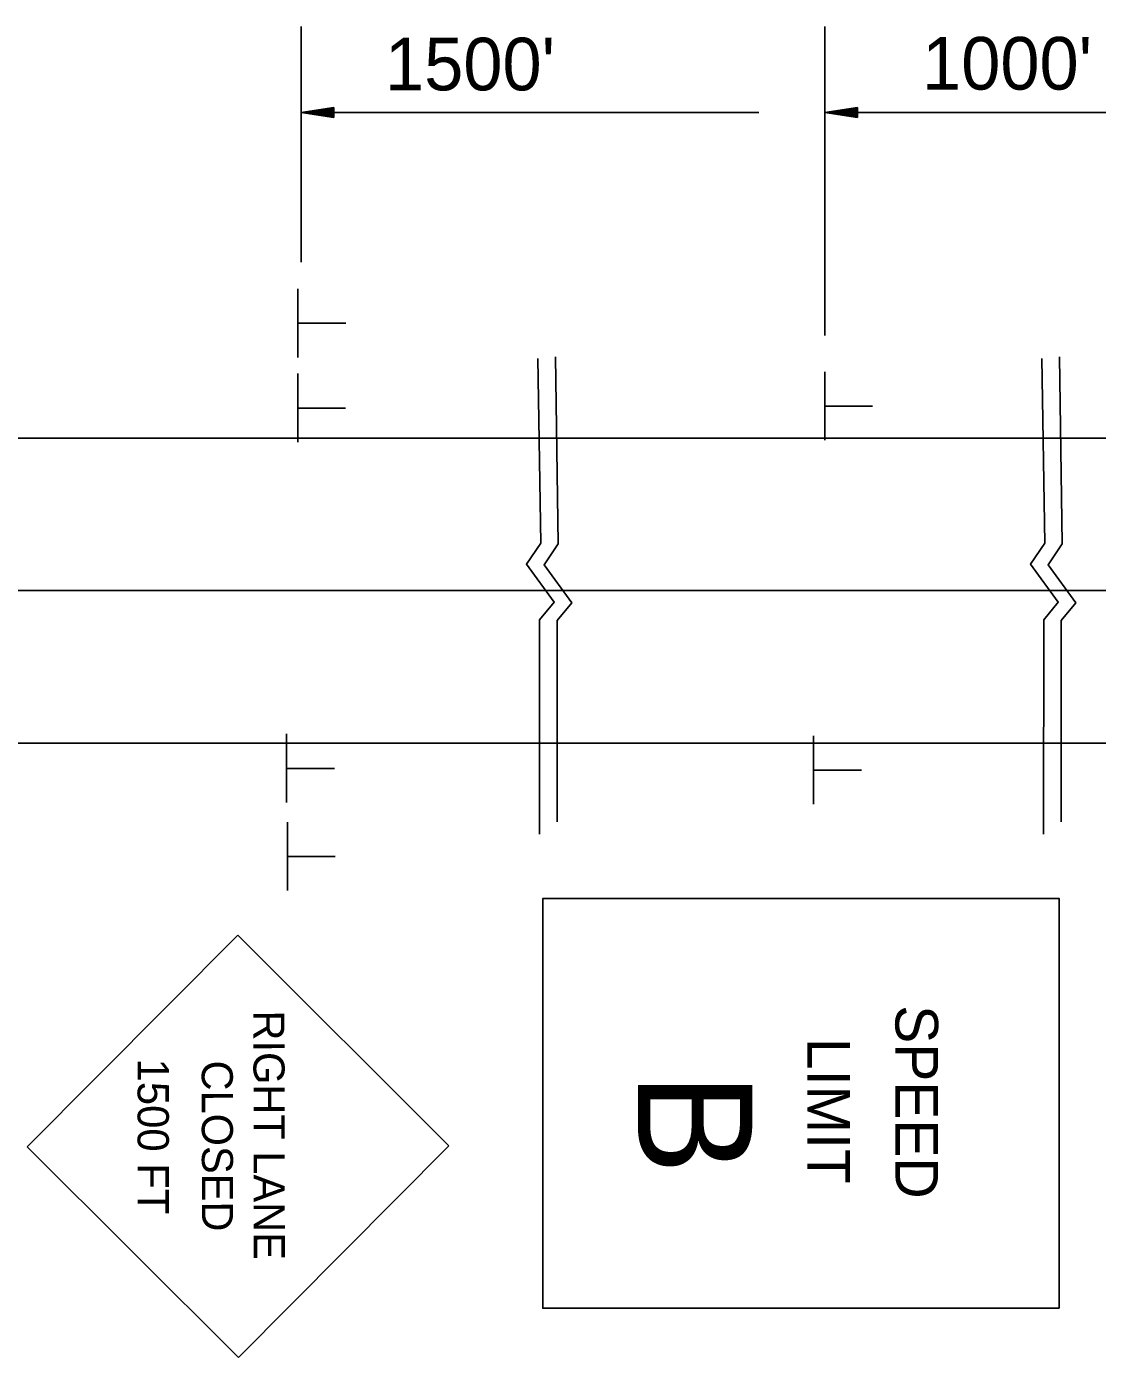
# Model space of a CAD drawing. Extents: x -500 to 213, y 382723 to 382830.
# Drawn here: x -257.04 to -244.84, y 382790.33 to 382805.5 of the extents above; entities that cross this region are included whole.
import ezdxf

# ---------------------------------------------------------------- set-up
doc = ezdxf.new("R2010")
doc.units = 0
doc.layers.add('Default', color=7, linetype='Continuous')

msp = doc.modelspace()

# ---------------------------------------------------------------- linework, layer by layer
at = {"layer": 'Default'}
for p, q in [((-253.914, 382805.499), (-253.914, 382802.814)), ((-247.944, 382805.499), (-247.944, 382801.978)), ((-253.539, 382804.576), (-253.914, 382804.52)), ((-253.539, 382804.464), (-253.539, 382804.576)), ((-247.569, 382804.576), (-247.944, 382804.52)), ((-247.569, 382804.464), (-247.569, 382804.576)), ((-253.914, 382804.52), (-248.695, 382804.52)), ((-253.539, 382804.464), (-253.914, 382804.52)), ((-253.539, 382804.567), (-253.851, 382804.52)), ((-253.539, 382804.473), (-253.851, 382804.52)), ((-253.539, 382804.557), (-253.786, 382804.52)), ((-253.539, 382804.482), (-253.786, 382804.52)), ((-253.539, 382804.548), (-253.724, 382804.52)), ((-253.539, 382804.492), (-253.724, 382804.52)), ((-253.539, 382804.538), (-253.66, 382804.52)), ((-253.539, 382804.502), (-253.66, 382804.52)), ((-253.539, 382804.529), (-253.598, 382804.52)), ((-253.539, 382804.511), (-253.598, 382804.52)), ((-247.944, 382804.52), (-242.726, 382804.52)), ((-247.569, 382804.464), (-247.944, 382804.52)), ((-247.569, 382804.567), (-247.882, 382804.52)), ((-247.569, 382804.473), (-247.882, 382804.52)), ((-247.569, 382804.557), (-247.817, 382804.52)), ((-247.569, 382804.482), (-247.817, 382804.52)), ((-247.569, 382804.548), (-247.755, 382804.52)), ((-247.569, 382804.492), (-247.755, 382804.52)), ((-247.569, 382804.538), (-247.691, 382804.52)), ((-247.569, 382804.502), (-247.691, 382804.52)), ((-247.569, 382804.529), (-247.629, 382804.52)), ((-247.569, 382804.511), (-247.629, 382804.52)), ((-253.95, 382801.728), (-253.95, 382802.51)), ((-253.938, 382802.117), (-253.404, 382802.117)), ((-253.952, 382800.762), (-253.952, 382801.544)), ((-247.944, 382800.783), (-247.944, 382801.565)), ((-253.94, 382801.151), (-253.406, 382801.151)), ((-247.933, 382801.172), (-247.399, 382801.172)), ((-260.198, 382800.808), (-251.538, 382800.808)), ((-251.538, 382800.808), (-235.546, 382800.808)), ((-260.198, 382799.07), (-251.538, 382799.07)), ((-251.538, 382799.07), (-235.546, 382799.07)), ((-260.198, 382797.331), (-250.621, 382797.331)), ((-254.078, 382796.655), (-254.078, 382797.438)), ((-251.538, 382797.331), (-235.546, 382797.331)), ((-248.071, 382796.634), (-248.071, 382797.416)), ((-254.067, 382797.044), (-253.532, 382797.044)), ((-248.059, 382797.023), (-247.525, 382797.023)), ((-254.069, 382795.65), (-254.069, 382796.432)), ((-254.058, 382796.039), (-253.524, 382796.039)), ((-257.037, 382792.731), (-254.635, 382795.141)), ((-252.227, 382792.739), (-254.635, 382795.141)), ((-254.627, 382790.329), (-257.037, 382792.731)), ((-254.627, 382790.329), (-252.227, 382792.739))]:
    msp.add_line(p, q, dxfattribs=at)
for points in [[(-251.213, 382801.716), (-251.181, 382799.612), (-251.344, 382799.371), (-251.027, 382798.938), (-251.194, 382798.738), (-251.194, 382796.292)], [(-251.014, 382801.735), (-250.982, 382799.604), (-251.144, 382799.362), (-250.828, 382798.929), (-250.994, 382798.729), (-250.995, 382796.433)], [(-245.468, 382801.716), (-245.436, 382799.612), (-245.598, 382799.371), (-245.281, 382798.938), (-245.448, 382798.738), (-245.449, 382796.292)], [(-245.268, 382801.735), (-245.236, 382799.604), (-245.398, 382799.362), (-245.082, 382798.929), (-245.248, 382798.729), (-245.249, 382796.433)]]:
    msp.add_lwpolyline(points, dxfattribs=at)
msp.add_lwpolyline([(-245.271, 382790.889), (-251.158, 382790.889), (-251.158, 382795.559), (-245.271, 382795.559)], close=True, dxfattribs=at)

# ---------------------------------------------------------------- texts
for s, p in [("1500'", (-252.956, 382804.772)), ("1000'", (-246.834, 382804.781))]:
    msp.add_text(s, height=0.6, dxfattribs=at).set_placement(p)
for s, height, rotation, p in [('SPEED', 0.4865, 270, (-247.138, 382794.344)), ('RIGHT LANE', 0.3544, 270.1004, (-254.457, 382794.284)), ('LIMIT', 0.4865, 270, (-248.143, 382793.971)), ('1500 FT', 0.3567, 270.0006, (-255.777, 382793.736)), ('CLOSED', 0.3543, 270.1003, (-255.046, 382793.713)), ('B', 1.304, 270, (-250.073, 382793.577))]:
    msp.add_text(s, height=height, rotation=rotation, dxfattribs=at).set_placement(p)

doc.saveas('drawing.dxf')
